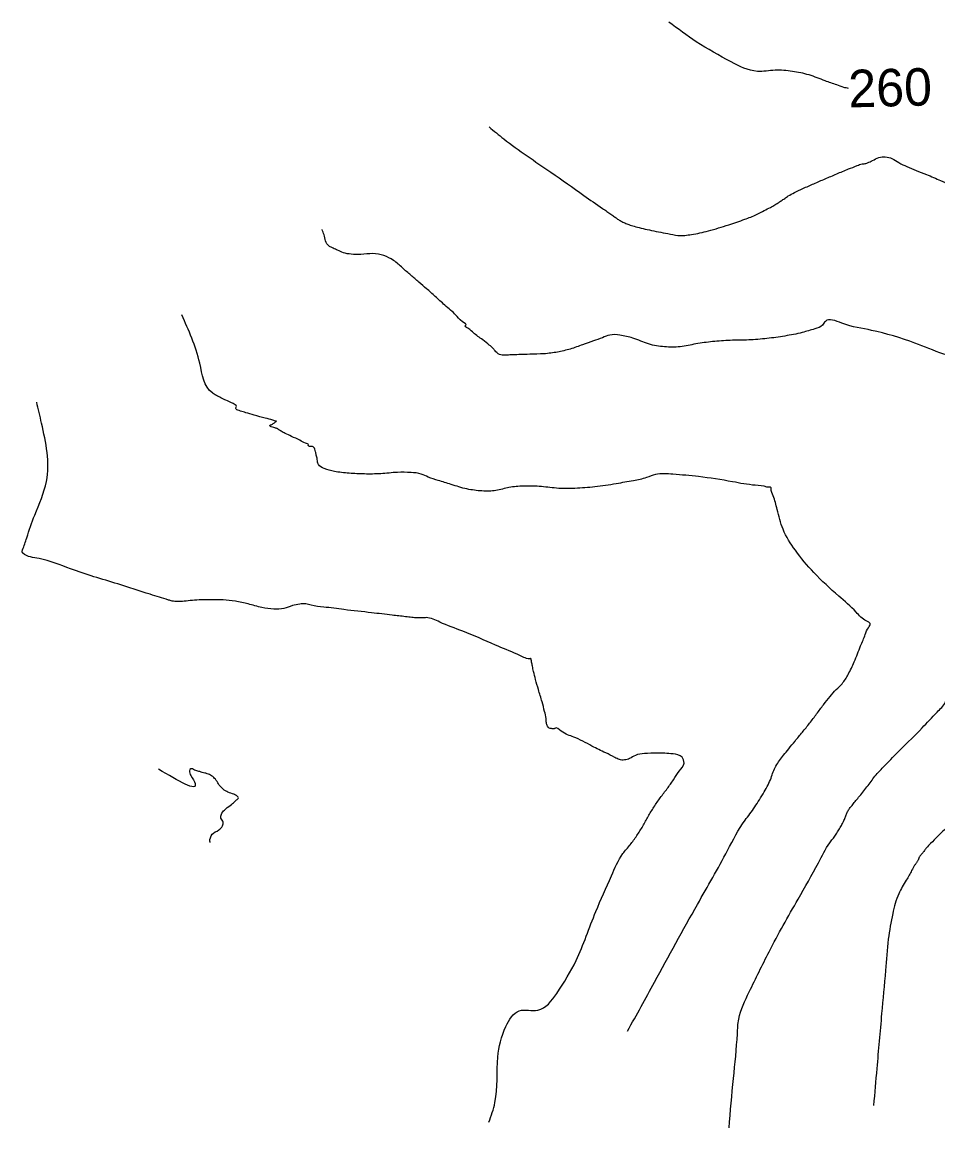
# Model space of a CAD drawing. Extents: x -478102 to -473059, y -1117705 to -1114104.
# Drawn here: x -476462.3 to -476364.6, y -1115563.8 to -1115445.8 of the extents above; entities that cross this region are included whole.
import ezdxf

# ---------------------------------------------------------------- set-up
doc = ezdxf.new("R2010")
doc.units = 0
for name, color, linetype in [('Vrstevnice_hlavni', 7, 'Continuous'), ('Vrstevnice_popis', 7, 'Continuous'), ('Vrstevnice_vedlejsi', 7, 'Continuous')]:
    doc.layers.add(name, color=color, linetype=linetype)

msp = doc.modelspace()

# ---------------------------------------------------------------- linework, layer by layer
at = {"layer": 'Vrstevnice_hlavni'}
for points in [[(-476374.118, -1115452.894), (-476374.632, -1115452.768), (-476375.379, -1115452.515), (-476376.616, -1115452.074), (-476378.342, -1115451.442), (-476380.123, -1115451.064), (-476381.96, -1115450.937), (-476383.851, -1115451.062), (-476386.654, -1115450.049), (-476390.368, -1115447.898), (-476393.306, -1115445.807)], [(-476442.249, -1115533.315), (-476442.258, -1115533.223), (-476442.035, -1115532.45), (-476441.322, -1115531.991), (-476440.926, -1115531.554), (-476440.848, -1115531.138), (-476441.086, -1115530.744), (-476441.04, -1115530.317), (-476440.708, -1115529.858), (-476440.091, -1115529.366), (-476439.638, -1115528.987), (-476439.349, -1115528.72), (-476439.224, -1115528.565), (-476439.347, -1115528.386), (-476439.718, -1115528.183), (-476440.335, -1115527.956), (-476440.852, -1115527.632), (-476441.268, -1115527.211), (-476441.584, -1115526.693), (-476441.969, -1115526.298), (-476442.426, -1115526.027), (-476442.953, -1115525.878), (-476443.443, -1115525.735), (-476443.895, -1115525.597), (-476444.309, -1115525.465), (-476444.44, -1115525.662), (-476444.286, -1115526.188), (-476443.849, -1115527.043), (-476447.74, -1115525.503)]]:
    msp.add_spline(points, degree=3, dxfattribs=at)
at = {"layer": 'Vrstevnice_vedlejsi'}
for points in [[(-476412.487, -1115456.977), (-476410.913, -1115458.262), (-476405.882, -1115461.815), (-476402.37, -1115464.29), (-476400.376, -1115465.685), (-476399.9, -1115466), (-476399.472, -1115466.293), (-476399.093, -1115466.564), (-476398.763, -1115466.813), (-476398.4, -1115467.035), (-476398.006, -1115467.232), (-476397.581, -1115467.402), (-476397, -1115467.583), (-476396.264, -1115467.775), (-476395.373, -1115467.977), (-476394.42, -1115468.176), (-476393.405, -1115468.369), (-476392.328, -1115468.558), (-476390.887, -1115468.463), (-476389.082, -1115468.084), (-476386.914, -1115467.422), (-476385.197, -1115466.84), (-476383.932, -1115466.337), (-476383.118, -1115465.915), (-476382.467, -1115465.566), (-476381.978, -1115465.291), (-476381.65, -1115465.088), (-476381.304, -1115464.864), (-476380.937, -1115464.618), (-476380.551, -1115464.349), (-476379.903, -1115463.998), (-476378.994, -1115463.563), (-476377.824, -1115463.044), (-476376.623, -1115462.523), (-476375.392, -1115462)], [(-476375.392, -1115462), (-476374.129, -1115461.473), (-476373.218, -1115461.118), (-476372.659, -1115460.933), (-476372.45, -1115460.919), (-476372.087, -1115460.802), (-476371.568, -1115460.58), (-476370.895, -1115460.255), (-476370.204, -1115460.181), (-476369.496, -1115460.36), (-476368.77, -1115460.791), (-476367.914, -1115461.219), (-476366.926, -1115461.642), (-476365.807, -1115462.062), (-476364.304, -1115462.716), (-476362.417, -1115463.605), (-476360.145, -1115464.728), (-476357.641, -1115465.438), (-476354.904, -1115465.734), (-476351.935, -1115465.618), (-476349.849, -1115465.502), (-476348.647, -1115465.387), (-476348.329, -1115465.272), (-476347.968, -1115465.34), (-476347.565, -1115465.59), (-476347.119, -1115466.023), (-476346.516, -1115466.573), (-476345.755, -1115467.242), (-476344.837, -1115468.03), (-476344.033, -1115469.141), (-476343.343, -1115470.576), (-476342.768, -1115472.335), (-476342.342, -1115473.633), (-476342.065, -1115474.468), (-476341.938, -1115474.841), (-476341.36, -1115475.721), (-476340.333, -1115477.106), (-476338.856, -1115478.997), (-476337.825, -1115480.446), (-476337.242, -1115481.454), (-476337.106, -1115482.02), (-476336.708, -1115482.699), (-476336.047, -1115483.489), (-476335.123, -1115484.392), (-476334.613, -1115485.234), (-476334.515, -1115486.014), (-476334.83, -1115486.732), (-476335.165, -1115487.505), (-476335.519, -1115488.332), (-476335.893, -1115489.212), (-476336.181, -1115489.954), (-476336.384, -1115490.556), (-476336.5, -1115491.018), (-476336.678, -1115491.638), (-476336.918, -1115492.417), (-476337.22, -1115493.354), (-476337.658, -1115494.21), (-476338.234, -1115494.984), (-476338.946, -1115495.678), (-476339.549, -1115496.226), (-476340.042, -1115496.627), (-476340.425, -1115496.883), (-476340.759, -1115497.34), (-476341.045, -1115497.997), (-476341.282, -1115498.856), (-476341.828, -1115499.854), (-476342.682, -1115500.993), (-476343.846, -1115502.272), (-476344.811, -1115503.411), (-476345.578, -1115504.411), (-476346.146, -1115505.272), (-476346.807, -1115506.216), (-476347.56, -1115507.242), (-476348.405, -1115508.352), (-476349.595, -1115510.321), (-476351.128, -1115513.152), (-476353.005, -1115516.842), (-476354.314, -1115519.344), (-476355.055, -1115520.656), (-476355.227, -1115520.78), (-476355.538, -1115521.104), (-476355.989, -1115521.629), (-476356.58, -1115522.354), (-476357.559, -1115523.662), (-476358.927, -1115525.554), (-476360.684, -1115528.028), (-476362.218, -1115530.038), (-476363.528, -1115531.584), (-476364.614, -1115532.666), (-476365.375, -1115533.438), (-476365.811, -1115533.898), (-476365.922, -1115534.047), (-476366.035, -1115534.195), (-476366.151, -1115534.34), (-476366.269, -1115534.483), (-476366.37, -1115534.607), (-476366.453, -1115534.711)], [(-476390.415, -1115480.123), (-476392.093, -1115480.442), (-476393.773, -1115480.449), (-476395.455, -1115480.141), (-476397.138, -1115479.52), (-476398.521, -1115479.202), (-476399.606, -1115479.187), (-476400.391, -1115479.474), (-476401.353, -1115479.819), (-476402.494, -1115480.221), (-476403.813, -1115480.681), (-476405.189, -1115481.004), (-476406.622, -1115481.191), (-476408.113, -1115481.24), (-476409.287, -1115481.28), (-476410.144, -1115481.31), (-476410.685, -1115481.331), (-476411.093, -1115481.319), (-476411.368, -1115481.273), (-476411.51, -1115481.194), (-476411.664, -1115481.065), (-476411.83, -1115480.886), (-476412.009, -1115480.658), (-476412.452, -1115480.262), (-476413.159, -1115479.699), (-476414.132, -1115478.968), (-476414.756, -1115478.466), (-476415.033, -1115478.195), (-476414.961, -1115478.152), (-476415.298, -1115477.773), (-476416.042, -1115477.057), (-476417.195, -1115476.004), (-476418.233, -1115475.067), (-476419.157, -1115474.246), (-476419.967, -1115473.541), (-476420.822, -1115472.803), (-476421.721, -1115472.032), (-476422.665, -1115471.228), (-476423.717, -1115470.72), (-476424.877, -1115470.508), (-476426.145, -1115470.593), (-476427.196, -1115470.561), (-476428.028, -1115470.413), (-476428.643, -1115470.148), (-476429.106, -1115469.938), (-476429.418, -1115469.785), (-476429.579, -1115469.688), (-476430.087, -1115468.492), (-476430.298, -1115467.927)], [(-476435.156, -1115488.388), (-476435.158, -1115488.388), (-476435.557, -1115488.278), (-476436.352, -1115488.058), (-476437.543, -1115487.729), (-476438.431, -1115487.476), (-476439.016, -1115487.299), (-476439.298, -1115487.198), (-476439.46, -1115487.083), (-476439.502, -1115486.954), (-476439.423, -1115486.81), (-476439.571, -1115486.628), (-476439.947, -1115486.406), (-476440.549, -1115486.147), (-476441.093, -1115485.887), (-476441.577, -1115485.629), (-476442.002, -1115485.371), (-476443.347, -1115482.202), (-476445.27, -1115477.051)], [(-476386.868, -1115563.77), (-476386.404, -1115558.49), (-476385.983, -1115553.73), (-476385.843, -1115552.17), (-476384.718, -1115549.256), (-476382.607, -1115544.988), (-476379.51, -1115539.367), (-476377.347, -1115535.488), (-476376.117, -1115533.352), (-476375.821, -1115532.959), (-476375.527, -1115532.539), (-476375.236, -1115532.091), (-476374.948, -1115531.616), (-476374.711, -1115531.173), (-476374.526, -1115530.763), (-476374.393, -1115530.385), (-476374.22, -1115530.026), (-476374.008, -1115529.686), (-476373.756, -1115529.365), (-476373.437, -1115528.968), (-476373.052, -1115528.496), (-476372.6, -1115527.948), (-476372.158, -1115527.393), (-476371.726, -1115526.831), (-476371.304, -1115526.261), (-476370.255, -1115525.116), (-476368.58, -1115523.398), (-476366.278, -1115521.105), (-476364.681, -1115519.417), (-476363.788, -1115518.333), (-476363.599, -1115517.854), (-476363.38, -1115517.403), (-476363.131, -1115516.981), (-476362.852, -1115516.586), (-476362.624, -1115516.208), (-476362.447, -1115515.848), (-476362.32, -1115515.506), (-476362.183, -1115515.228), (-476362.036, -1115515.015), (-476361.879, -1115514.866), (-476361.743, -1115514.589), (-476361.628, -1115514.182), (-476361.535, -1115513.647), (-476361.302, -1115513.008), (-476360.931, -1115512.265), (-476360.421, -1115511.418), (-476359.844, -1115510.674), (-476359.201, -1115510.032), (-476358.493, -1115509.493), (-476357.886, -1115508.861), (-476357.381, -1115508.138), (-476356.978, -1115507.323), (-476356.457, -1115506.284), (-476355.818, -1115505.02), (-476355.061, -1115503.532), (-476354.274, -1115502.169), (-476353.457, -1115500.932), (-476352.611, -1115499.821), (-476352.458, -1115498.76), (-476353, -1115497.749), (-476354.236, -1115496.789), (-476355.796, -1115495.443), (-476357.679, -1115493.713), (-476359.885, -1115491.598), (-476361.477, -1115490.015), (-476362.455, -1115488.962), (-476362.82, -1115488.441), (-476362.968, -1115487.633), (-476362.899, -1115486.539), (-476362.614, -1115485.158), (-476362.433, -1115483.976), (-476362.356, -1115482.993), (-476362.383, -1115482.21), (-476363.943, -1115481.232), (-476367.039, -1115480.058), (-476371.668, -1115478.69), (-476374.855, -1115477.913), (-476376.599, -1115477.729), (-476376.9, -1115478.137), (-476377.722, -1115478.533), (-476379.064, -1115478.919), (-476380.926, -1115479.294), (-476382.829, -1115479.558), (-476384.771, -1115479.713), (-476386.754, -1115479.758), (-476388.635, -1115479.895), (-476390.415, -1115480.123)], [(-476408.095, -1115513.705), (-476408.196, -1115513.728), (-476408.268, -1115513.743), (-476408.31, -1115513.748), (-476408.321, -1115513.745), (-476409.488, -1115513.249), (-476411.808, -1115512.262), (-476415.283, -1115510.782), (-476417.744, -1115509.807), (-476419.192, -1115509.336), (-476419.626, -1115509.37), (-476420.137, -1115509.365), (-476420.725, -1115509.322), (-476421.39, -1115509.24), (-476422.819, -1115509.072), (-476425.012, -1115508.818), (-476427.967, -1115508.478), (-476430.119, -1115508.208), (-476431.467, -1115508.009), (-476432.012, -1115507.881), (-476432.677, -1115507.898), (-476433.462, -1115508.059), (-476434.367, -1115508.365), (-476435.455, -1115508.435), (-476436.726, -1115508.27), (-476438.179, -1115507.87), (-476439.551, -1115507.597), (-476440.841, -1115507.45), (-476442.049, -1115507.43), (-476443.148, -1115507.446), (-476444.139, -1115507.499), (-476445.02, -1115507.589), (-476445.738, -1115507.612), (-476446.294, -1115507.568), (-476446.687, -1115507.457), (-476448.623, -1115506.848), (-476452.103, -1115505.741), (-476457.127, -1115504.136), (-476460.496, -1115503.043), (-476462.21, -1115502.463), (-476462.27, -1115502.394), (-476462.297, -1115502.311), (-476462.291, -1115502.212), (-476462.252, -1115502.098), (-476461.808, -1115500.826), (-476460.959, -1115498.396), (-476459.705, -1115494.808), (-476460.221, -1115488.599), (-476460.746, -1115486.336)], [(-476381.496, -1115524.576), (-476381.058, -1115524.018), (-476380.504, -1115523.329), (-476379.834, -1115522.508), (-476379.049, -1115521.557), (-476378.281, -1115520.592), (-476377.53, -1115519.614), (-476376.797, -1115518.624), (-476376.099, -1115517.755), (-476375.438, -1115517.009), (-476374.812, -1115516.386), (-476374.17, -1115515.401), (-476373.512, -1115514.054), (-476372.838, -1115512.345), (-476372.335, -1115511.13), (-476372.003, -1115510.408), (-476371.84, -1115510.178), (-476371.827, -1115509.979), (-476371.962, -1115509.811), (-476372.246, -1115509.672), (-476373.318, -1115508.746), (-476375.177, -1115507.032), (-476377.825, -1115504.531), (-476379.802, -1115502.156), (-476381.109, -1115499.909), (-476381.745, -1115497.789), (-476382.17, -1115496.348), (-476382.383, -1115495.585), (-476382.386, -1115495.5), (-476382.424, -1115495.445), (-476382.499, -1115495.418), (-476382.61, -1115495.421), (-476382.691, -1115495.424), (-476382.74, -1115495.427), (-476382.759, -1115495.431), (-476382.784, -1115495.429), (-476382.813, -1115495.421), (-476382.848, -1115495.408), (-476384.079, -1115495.216), (-476386.506, -1115494.845), (-476390.13, -1115494.294), (-476392.866, -1115494.036), (-476394.717, -1115494.071), (-476395.681, -1115494.399), (-476397.081, -1115494.728), (-476398.917, -1115495.058), (-476401.19, -1115495.39), (-476403.316, -1115495.546), (-476405.295, -1115495.527), (-476407.128, -1115495.333), (-476408.815, -1115495.309), (-476410.355, -1115495.455), (-476411.749, -1115495.772), (-476413.243, -1115495.824), (-476414.837, -1115495.61), (-476416.531, -1115495.132), (-476417.908, -1115494.707), (-476418.968, -1115494.337), (-476419.711, -1115494.02), (-476420.805, -1115493.856), (-476422.249, -1115493.843), (-476424.045, -1115493.982), (-476425.766, -1115494.011), (-476427.414, -1115493.928), (-476428.987, -1115493.735), (-476430.078, -1115493.424), (-476430.686, -1115492.995), (-476430.812, -1115492.449), (-476430.915, -1115491.994), (-476430.996, -1115491.631), (-476431.055, -1115491.359), (-476431.167, -1115491.175), (-476431.332, -1115491.079), (-476431.551, -1115491.071), (-476431.695, -1115491.04), (-476431.765, -1115490.986), (-476431.759, -1115490.908), (-476432.056, -1115490.718), (-476432.657, -1115490.416), (-476433.561, -1115490.002), (-476434.225, -1115489.683), (-476434.65, -1115489.461), (-476434.835, -1115489.334), (-476434.976, -1115489.24), (-476435.074, -1115489.18), (-476435.128, -1115489.153), (-476435.254, -1115489.108), (-476435.453, -1115489.045), (-476435.725, -1115488.965), (-476435.863, -1115488.891), (-476435.867, -1115488.824), (-476435.736, -1115488.763), (-476435.599, -1115488.688), (-476435.455, -1115488.598), (-476435.304, -1115488.493), (-476435.204, -1115488.423), (-476435.156, -1115488.388)], [(-476412.508, -1115563.171), (-476411.848, -1115561.069), (-476411.539, -1115556.209), (-476410.675, -1115552.946), (-476409.255, -1115551.281), (-476407.279, -1115551.213), (-476405.259, -1115549.425), (-476403.194, -1115545.916), (-476401.086, -1115540.688), (-476399.421, -1115536.885), (-476398.2, -1115534.51), (-476397.423, -1115533.561), (-476396.715, -1115532.584), (-476396.077, -1115531.58), (-476395.509, -1115530.549), (-476394.886, -1115529.538), (-476394.208, -1115528.545), (-476393.474, -1115527.573), (-476392.807, -1115526.632), (-476392.208, -1115525.724), (-476391.677, -1115524.848), (-476391.892, -1115524.233), (-476392.853, -1115523.879), (-476394.56, -1115523.785), (-476395.9, -1115523.836), (-476396.873, -1115524.031), (-476397.48, -1115524.372), (-476398.046, -1115524.521), (-476398.573, -1115524.479), (-476399.059, -1115524.246), (-476400.034, -1115523.767), (-476401.498, -1115523.043), (-476403.451, -1115522.073), (-476404.773, -1115521.441), (-476405.463, -1115521.147), (-476405.521, -1115521.191), (-476405.642, -1115521.2), (-476405.825, -1115521.174), (-476406.072, -1115521.112), (-476406.25, -1115520.912), (-476406.358, -1115520.574), (-476406.399, -1115520.096), (-476406.555, -1115519.343), (-476406.827, -1115518.313), (-476407.215, -1115517.007), (-476407.516, -1115515.936), (-476407.728, -1115515.1), (-476407.853, -1115514.499), (-476407.938, -1115514.074), (-476407.983, -1115513.826), (-476407.988, -1115513.754), (-476408.025, -1115513.714), (-476408.095, -1115513.705)], [(-476397.702, -1115553.445), (-476394.813, -1115548.217), (-476390.245, -1115539.924), (-476387.028, -1115534.168), (-476385.162, -1115530.949), (-476384.647, -1115530.266), (-476384.137, -1115529.535), (-476383.631, -1115528.757), (-476383.13, -1115527.931), (-476382.719, -1115527.161), (-476382.397, -1115526.448), (-476382.166, -1115525.791), (-476381.866, -1115525.167), (-476381.496, -1115524.576)], [(-476366.453, -1115534.711), (-476366.519, -1115534.795), (-476366.575, -1115534.884), (-476366.62, -1115534.978), (-476366.655, -1115535.077), (-476366.704, -1115535.185), (-476366.766, -1115535.301), (-476366.841, -1115535.425), (-476366.917, -1115535.543), (-476366.994, -1115535.653), (-476367.072, -1115535.756), (-476367.394, -1115536.315), (-476367.961, -1115537.331), (-476368.772, -1115538.804), (-476369.413, -1115540.903), (-476369.885, -1115543.629), (-476370.186, -1115546.981), (-476370.595, -1115551.582), (-476371.111, -1115557.431), (-476371.459, -1115561.384)]]:
    msp.add_spline(points, degree=3, dxfattribs=at)

# ---------------------------------------------------------------- texts
at = {"layer": 'Vrstevnice_popis'}
msp.add_text(' 260 ', height=4, rotation=1.48492, dxfattribs=at).set_placement((-476375.588, -1115454.953))

doc.saveas('drawing.dxf')
